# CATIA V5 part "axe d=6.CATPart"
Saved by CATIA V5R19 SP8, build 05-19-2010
Part number: axe d=6
Revision: ANY
Definition: UNKNOWN
Nomenclature: axe d=6
Source: Unknown
Bounding box of the stored display mesh (mm): x 0 to 16.4, y -3 to 3, z -3 to 3
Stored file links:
  D:\Documents\1_Travail\1 - ac-limoges.fr\ac-limoges.fr\Emmanuel Maynard - STI2D_Turgot\2 -2I2D\2_SEQUENCE_Serrure_Biométrique\5-Spé_ITEC\Serrure_Bio_Eleve\axe d=6.CATPart
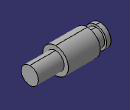
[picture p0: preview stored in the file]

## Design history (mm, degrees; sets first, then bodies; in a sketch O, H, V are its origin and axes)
Body1 "Révolution1" (main body)
  Solid1: solid without history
